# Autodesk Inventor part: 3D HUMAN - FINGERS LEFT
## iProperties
Category: PART
Company: Cross Bros.
Shininess: 64.0
Length Units: 11272
Angle Units: 11279
Time Units: 11290
Mass Units: 11286
Length Display Precision: 3
Angle Display Precision: 2
Compacted: True
Part Number: 3D HUMAN - FINGERS LEFT
Document SubType Name: Modeling
Created: 2003-03
Designer: MVF
Catalog Web Link: www.crossbros.com
Density: 0.0
Volumn: 0.0
Area: 0.0
PropertySet Name: Model Information
Control State: 0
Master: False
Checked Out: False
Author: MVF
Title: iMike
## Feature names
1. Extrusion1
2. Extrusion2
3. Fillet1
4. Fillet3
5. Fillet4
